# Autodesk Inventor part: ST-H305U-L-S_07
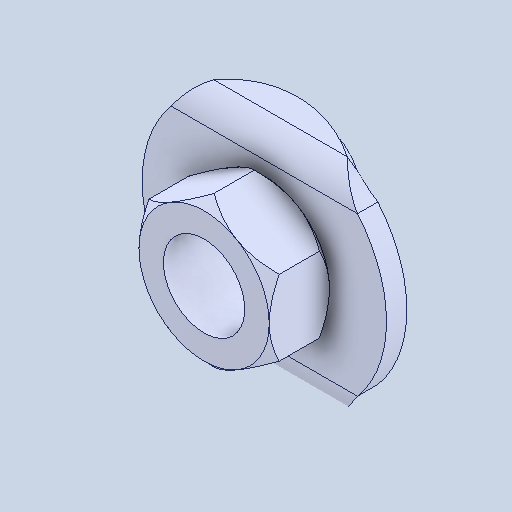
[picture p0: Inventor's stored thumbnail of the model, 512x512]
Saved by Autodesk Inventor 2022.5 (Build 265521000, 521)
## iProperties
Created: 2024-07
Part Number: ST-H305U-L-S_07
Material: 一般
Document SubType Name: Modeling
Designer: ImaoCorp
Density: 1 g/cm^3
Appearance: 既定
Author: ImaoCorp
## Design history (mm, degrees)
feature "ST-H305U-L-S_07"
node "ソリッド1"
